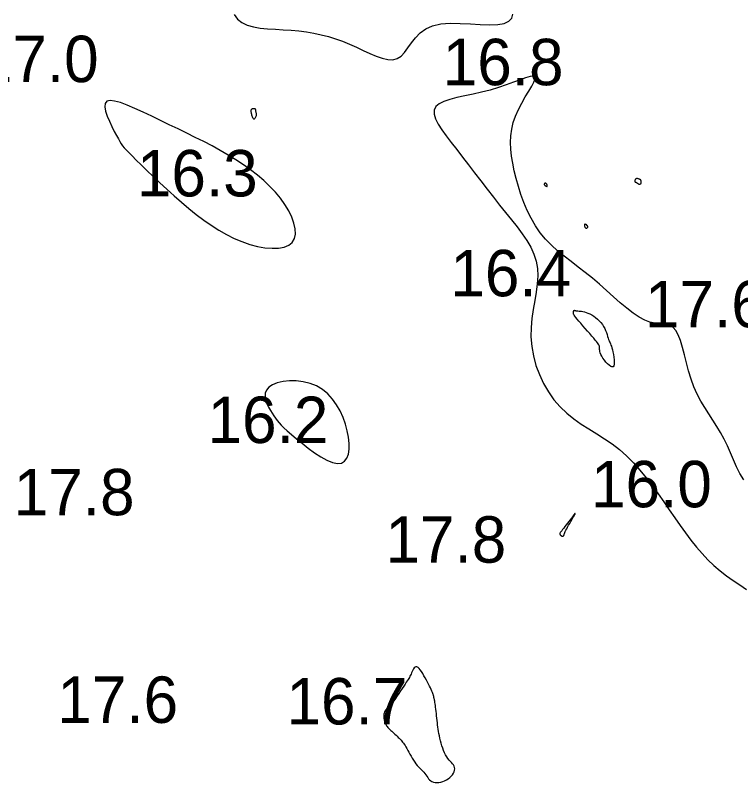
# Model space of a CAD drawing. Extents: x 3040093 to 3056816, y 408076 to 509144.
# Drawn here: x 3045488.3 to 3045566.4, y 434025.2 to 434107.9 of the extents above; entities that cross this region are included whole.
import ezdxf

# ---------------------------------------------------------------- set-up
doc = ezdxf.new("R2010")
doc.units = 0
doc.layers.add('V-CHAN-CONT-EL17', color=7, linetype='Continuous')
doc.layers.add('V-TOPO-SOUN-0610', color=7, linetype='Continuous')

msp = doc.modelspace()

# ---------------------------------------------------------------- linework, layer by layer
at = {"layer": 'V-CHAN-CONT-EL17'}
for points in [[(3045511.894, 434107.966), (3045512.24, 434107.481), (3045512.706, 434107.108), (3045513.282, 434106.836), (3045513.95, 434106.645), (3045514.69, 434106.517), (3045515.484, 434106.435), (3045516.315, 434106.381), (3045517.164, 434106.335), (3045518.013, 434106.281), (3045518.846, 434106.202), (3045519.663, 434106.095), (3045520.464, 434105.958), (3045521.252, 434105.79), (3045522.029, 434105.591), (3045522.795, 434105.358), (3045523.554, 434105.092), (3045524.307, 434104.789), (3045525.054, 434104.455), (3045525.787, 434104.109), (3045526.5, 434103.777), (3045527.183, 434103.485), (3045527.828, 434103.258), (3045528.427, 434103.121), (3045528.971, 434103.1), (3045529.451, 434103.221), (3045529.867, 434103.498), (3045530.24, 434103.901), (3045530.6, 434104.392), (3045530.978, 434104.931), (3045531.401, 434105.477), (3045531.901, 434105.991), (3045532.505, 434106.433), (3045533.245, 434106.764), (3045534.136, 434106.956), (3045535.143, 434107.032), (3045536.22, 434107.026), (3045537.318, 434106.975), (3045538.39, 434106.914), (3045539.388, 434106.877), (3045540.265, 434106.9), (3045540.972, 434107.018), (3045541.474, 434107.256), (3045541.774, 434107.598), (3045541.887, 434108.019)], [(3045566.758, 434057.837), (3045566.34, 434058.526), (3045565.974, 434059.251), (3045565.641, 434059.999), (3045565.322, 434060.754), (3045564.999, 434061.503), (3045564.653, 434062.232), (3045564.27, 434062.931), (3045563.857, 434063.608), (3045563.425, 434064.274), (3045562.987, 434064.941), (3045562.552, 434065.621), (3045562.134, 434066.326), (3045561.743, 434067.067), (3045561.39, 434067.857), (3045561.085, 434068.701), (3045560.819, 434069.577), (3045560.582, 434070.457), (3045560.363, 434071.313), (3045560.152, 434072.117), (3045559.938, 434072.841), (3045559.71, 434073.457), (3045559.457, 434073.936), (3045559.171, 434074.262), (3045558.849, 434074.46), (3045558.49, 434074.567), (3045558.092, 434074.621), (3045557.655, 434074.659), (3045557.178, 434074.716), (3045556.658, 434074.831), (3045556.096, 434075.039), (3045555.492, 434075.369), (3045554.849, 434075.808), (3045554.172, 434076.336), (3045553.466, 434076.932), (3045552.737, 434077.573), (3045551.989, 434078.24), (3045551.228, 434078.91), (3045550.458, 434079.562), (3045549.686, 434080.181), (3045548.918, 434080.774), (3045548.162, 434081.353), (3045547.426, 434081.931), (3045546.717, 434082.519), (3045546.045, 434083.13), (3045545.416, 434083.776), (3045544.838, 434084.47), (3045544.317, 434085.22), (3045543.852, 434086.019), (3045543.439, 434086.853), (3045543.076, 434087.712), (3045542.759, 434088.583), (3045542.485, 434089.454), (3045542.25, 434090.314), (3045542.052, 434091.151), (3045541.889, 434091.954), (3045541.764, 434092.728), (3045541.685, 434093.477), (3045541.657, 434094.206), (3045541.687, 434094.921), (3045541.78, 434095.626), (3045541.943, 434096.328), (3045542.181, 434097.032), (3045542.494, 434097.738), (3045542.857, 434098.432), (3045543.237, 434099.095), (3045543.603, 434099.707), (3045543.921, 434100.249), (3045544.16, 434100.703), (3045544.288, 434101.049), (3045544.272, 434101.269), (3045544.089, 434101.349), (3045543.748, 434101.308), (3045543.269, 434101.168), (3045542.67, 434100.954), (3045541.97, 434100.69), (3045541.186, 434100.399), (3045540.338, 434100.105), (3045539.444, 434099.833), (3045538.524, 434099.599), (3045537.603, 434099.396), (3045536.71, 434099.211), (3045535.87, 434099.028), (3045535.112, 434098.835), (3045534.462, 434098.616), (3045533.947, 434098.359), (3045533.595, 434098.049), (3045533.424, 434097.675), (3045533.423, 434097.236), (3045533.572, 434096.737), (3045533.849, 434096.179), (3045534.236, 434095.567), (3045534.711, 434094.901), (3045535.255, 434094.186), (3045535.848, 434093.424), (3045536.472, 434092.62), (3045537.117, 434091.782), (3045537.779, 434090.921), (3045538.452, 434090.048), (3045539.128, 434089.171), (3045539.802, 434088.303), (3045540.468, 434087.453), (3045541.119, 434086.632), (3045541.749, 434085.846), (3045542.347, 434085.09), (3045542.899, 434084.354), (3045543.394, 434083.627), (3045543.82, 434082.901), (3045544.164, 434082.166), (3045544.414, 434081.413), (3045544.557, 434080.63), (3045544.588, 434079.812), (3045544.529, 434078.959), (3045544.407, 434078.073), (3045544.25, 434077.156), (3045544.087, 434076.213), (3045543.945, 434075.245), (3045543.852, 434074.255), (3045543.837, 434073.246), (3045543.921, 434072.223), (3045544.105, 434071.196), (3045544.383, 434070.179), (3045544.748, 434069.185), (3045545.196, 434068.229), (3045545.721, 434067.322), (3045546.317, 434066.479), (3045546.977, 434065.713), (3045547.696, 434065.031), (3045548.463, 434064.419), (3045549.264, 434063.858), (3045550.09, 434063.326), (3045550.926, 434062.804), (3045551.761, 434062.272), (3045552.584, 434061.709), (3045553.382, 434061.097), (3045554.146, 434060.419), (3045554.877, 434059.681), (3045555.577, 434058.895), (3045556.25, 434058.071), (3045556.9, 434057.22), (3045557.529, 434056.353), (3045558.141, 434055.48), (3045558.74, 434054.613), (3045559.328, 434053.76), (3045559.91, 434052.928), (3045560.492, 434052.121), (3045561.077, 434051.344), (3045561.671, 434050.6), (3045562.278, 434049.894), (3045562.903, 434049.231), (3045563.551, 434048.614), (3045564.224, 434048.046), (3045564.919, 434047.517), (3045565.63, 434047.014), (3045566.349, 434046.524), (3045567.072, 434046.035)]]:
    msp.add_lwpolyline(points, dxfattribs=at)
for points in [[(3045506.998, 434087.081), (3045507.797, 434086.438), (3045508.6, 434085.831), (3045509.407, 434085.265), (3045510.22, 434084.744), (3045511.04, 434084.273), (3045511.868, 434083.859), (3045512.706, 434083.505), (3045513.552, 434083.217), (3045514.39, 434083), (3045515.199, 434082.858), (3045515.961, 434082.796), (3045516.656, 434082.817), (3045517.264, 434082.928), (3045517.766, 434083.131), (3045518.143, 434083.432), (3045518.379, 434083.831), (3045518.48, 434084.317), (3045518.458, 434084.874), (3045518.322, 434085.486), (3045518.084, 434086.138), (3045517.754, 434086.813), (3045517.342, 434087.498), (3045516.861, 434088.175), (3045516.318, 434088.831), (3045515.721, 434089.466), (3045515.073, 434090.079), (3045514.378, 434090.671), (3045513.642, 434091.243), (3045512.87, 434091.794), (3045512.064, 434092.326), (3045511.231, 434092.84), (3045510.375, 434093.335), (3045509.497, 434093.816), (3045508.602, 434094.284), (3045507.691, 434094.744), (3045506.767, 434095.197), (3045505.833, 434095.648), (3045504.892, 434096.099), (3045503.946, 434096.553), (3045503, 434097.01), (3045502.074, 434097.452), (3045501.19, 434097.859), (3045500.37, 434098.209), (3045499.636, 434098.482), (3045499.009, 434098.656), (3045498.512, 434098.71), (3045498.168, 434098.624), (3045497.989, 434098.385), (3045497.955, 434098.018), (3045498.038, 434097.554), (3045498.211, 434097.027), (3045498.443, 434096.469), (3045498.707, 434095.913), (3045498.975, 434095.391), (3045499.217, 434094.936), (3045499.414, 434094.571), (3045499.576, 434094.282), (3045499.722, 434094.043), (3045499.872, 434093.83), (3045500.045, 434093.618), (3045500.259, 434093.383), (3045500.534, 434093.101), (3045500.888, 434092.746), (3045501.336, 434092.301), (3045501.87, 434091.775), (3045502.478, 434091.181), (3045503.148, 434090.537), (3045503.867, 434089.857), (3045504.624, 434089.156), (3045505.406, 434088.45), (3045506.2, 434087.754)], [(3045514.008, 434096.739), (3045514.054, 434096.753), (3045514.1, 434096.785), (3045514.144, 434096.831), (3045514.185, 434096.887), (3045514.221, 434096.95), (3045514.25, 434097.017), (3045514.271, 434097.084), (3045514.282, 434097.148), (3045514.285, 434097.209), (3045514.282, 434097.267), (3045514.274, 434097.322), (3045514.262, 434097.375), (3045514.25, 434097.425), (3045514.238, 434097.474), (3045514.229, 434097.521), (3045514.222, 434097.567), (3045514.218, 434097.61), (3045514.215, 434097.652), (3045514.209, 434097.69), (3045514.2, 434097.724), (3045514.186, 434097.754), (3045514.164, 434097.78), (3045514.133, 434097.8), (3045514.092, 434097.814), (3045514.043, 434097.822), (3045513.988, 434097.824), (3045513.93, 434097.821), (3045513.872, 434097.812), (3045513.818, 434097.798), (3045513.769, 434097.778), (3045513.728, 434097.753), (3045513.698, 434097.723), (3045513.679, 434097.687), (3045513.668, 434097.646), (3045513.666, 434097.597), (3045513.67, 434097.542), (3045513.681, 434097.48), (3045513.696, 434097.41), (3045513.714, 434097.331), (3045513.736, 434097.245), (3045513.76, 434097.154), (3045513.786, 434097.062), (3045513.816, 434096.975), (3045513.848, 434096.895), (3045513.883, 434096.828), (3045513.922, 434096.777), (3045513.963, 434096.746)], [(3045555.478, 434089.709), (3045555.514, 434089.705), (3045555.552, 434089.706), (3045555.588, 434089.712), (3045555.622, 434089.724), (3045555.653, 434089.74), (3045555.68, 434089.761), (3045555.7, 434089.788), (3045555.713, 434089.819), (3045555.721, 434089.854), (3045555.723, 434089.891), (3045555.722, 434089.93), (3045555.717, 434089.968), (3045555.71, 434090.005), (3045555.703, 434090.039), (3045555.695, 434090.07), (3045555.689, 434090.095), (3045555.682, 434090.116), (3045555.674, 434090.133), (3045555.664, 434090.149), (3045555.65, 434090.163), (3045555.63, 434090.177), (3045555.605, 434090.192), (3045555.572, 434090.209), (3045555.531, 434090.228), (3045555.483, 434090.249), (3045555.431, 434090.269), (3045555.376, 434090.286), (3045555.32, 434090.299), (3045555.265, 434090.305), (3045555.213, 434090.304), (3045555.167, 434090.292), (3045555.127, 434090.27), (3045555.094, 434090.238), (3045555.068, 434090.199), (3045555.049, 434090.156), (3045555.036, 434090.112), (3045555.029, 434090.068), (3045555.029, 434090.027), (3045555.035, 434089.992), (3045555.047, 434089.965), (3045555.063, 434089.944), (3045555.084, 434089.929), (3045555.109, 434089.917), (3045555.135, 434089.908), (3045555.163, 434089.898), (3045555.191, 434089.888), (3045555.219, 434089.875), (3045555.246, 434089.858), (3045555.272, 434089.838), (3045555.298, 434089.816), (3045555.324, 434089.793), (3045555.351, 434089.771), (3045555.38, 434089.75), (3045555.41, 434089.732), (3045555.442, 434089.718)], [(3045545.599, 434089.481), (3045545.602, 434089.506), (3045545.599, 434089.537), (3045545.589, 434089.573), (3045545.576, 434089.612), (3045545.559, 434089.65), (3045545.54, 434089.686), (3045545.52, 434089.718), (3045545.502, 434089.744), (3045545.484, 434089.765), (3045545.467, 434089.78), (3045545.45, 434089.791), (3045545.434, 434089.798), (3045545.419, 434089.802), (3045545.403, 434089.803), (3045545.389, 434089.803), (3045545.374, 434089.802), (3045545.36, 434089.799), (3045545.347, 434089.795), (3045545.334, 434089.789), (3045545.322, 434089.782), (3045545.31, 434089.773), (3045545.3, 434089.763), (3045545.29, 434089.751), (3045545.282, 434089.736), (3045545.276, 434089.72), (3045545.272, 434089.703), (3045545.272, 434089.683), (3045545.276, 434089.662), (3045545.285, 434089.639), (3045545.301, 434089.615), (3045545.323, 434089.589), (3045545.352, 434089.562), (3045545.387, 434089.535), (3045545.425, 434089.51), (3045545.464, 434089.489), (3045545.501, 434089.472), (3045545.536, 434089.461), (3045545.565, 434089.458), (3045545.586, 434089.464)], [(3045549.87, 434084.971), (3045549.89, 434084.986), (3045549.908, 434085.003), (3045549.925, 434085.023), (3045549.94, 434085.043), (3045549.952, 434085.063), (3045549.962, 434085.083), (3045549.967, 434085.102), (3045549.969, 434085.12), (3045549.967, 434085.135), (3045549.963, 434085.149), (3045549.956, 434085.162), (3045549.948, 434085.173), (3045549.938, 434085.183), (3045549.929, 434085.191), (3045549.919, 434085.199), (3045549.91, 434085.205), (3045549.902, 434085.211), (3045549.895, 434085.216), (3045549.888, 434085.22), (3045549.883, 434085.225), (3045549.879, 434085.229), (3045549.876, 434085.234), (3045549.874, 434085.239), (3045549.874, 434085.245), (3045549.874, 434085.251), (3045549.873, 434085.259), (3045549.87, 434085.267), (3045549.865, 434085.277), (3045549.857, 434085.288), (3045549.844, 434085.301), (3045549.825, 434085.314), (3045549.801, 434085.33), (3045549.772, 434085.345), (3045549.74, 434085.359), (3045549.707, 434085.369), (3045549.675, 434085.376), (3045549.646, 434085.376), (3045549.622, 434085.369), (3045549.605, 434085.352), (3045549.595, 434085.326), (3045549.593, 434085.291), (3045549.597, 434085.25), (3045549.607, 434085.205), (3045549.621, 434085.159), (3045549.638, 434085.113), (3045549.658, 434085.07), (3045549.678, 434085.033), (3045549.7, 434085.002), (3045549.721, 434084.979), (3045549.743, 434084.962), (3045549.764, 434084.951), (3045549.786, 434084.945), (3045549.807, 434084.945), (3045549.828, 434084.95), (3045549.849, 434084.958)], [(3045551.215, 434072.234), (3045551.19, 434072.312), (3045551.149, 434072.398), (3045551.089, 434072.494), (3045551.007, 434072.608), (3045550.9, 434072.744), (3045550.765, 434072.908), (3045550.598, 434073.104), (3045550.398, 434073.336), (3045550.173, 434073.596), (3045549.932, 434073.873), (3045549.684, 434074.158), (3045549.44, 434074.44), (3045549.208, 434074.709), (3045548.998, 434074.955), (3045548.82, 434075.168), (3045548.68, 434075.34), (3045548.576, 434075.474), (3045548.503, 434075.576), (3045548.455, 434075.651), (3045548.427, 434075.705), (3045548.414, 434075.743), (3045548.411, 434075.772), (3045548.413, 434075.795), (3045548.415, 434075.819), (3045548.416, 434075.844), (3045548.417, 434075.869), (3045548.419, 434075.895), (3045548.42, 434075.921), (3045548.423, 434075.946), (3045548.426, 434075.971), (3045548.431, 434075.995), (3045548.437, 434076.018), (3045548.444, 434076.039), (3045548.453, 434076.059), (3045548.463, 434076.076), (3045548.473, 434076.09), (3045548.485, 434076.101), (3045548.497, 434076.108), (3045548.51, 434076.111), (3045548.523, 434076.11), (3045548.54, 434076.106), (3045548.561, 434076.098), (3045548.589, 434076.088), (3045548.626, 434076.077), (3045548.674, 434076.066), (3045548.736, 434076.056), (3045548.813, 434076.047), (3045548.907, 434076.039), (3045549.018, 434076.032), (3045549.145, 434076.02), (3045549.287, 434076.002), (3045549.443, 434075.975), (3045549.611, 434075.936), (3045549.792, 434075.882), (3045549.984, 434075.81), (3045550.186, 434075.718), (3045550.393, 434075.606), (3045550.603, 434075.476), (3045550.81, 434075.329), (3045551.011, 434075.165), (3045551.201, 434074.987), (3045551.377, 434074.794), (3045551.534, 434074.589), (3045551.67, 434074.373), (3045551.785, 434074.151), (3045551.883, 434073.926), (3045551.967, 434073.705), (3045552.038, 434073.492), (3045552.101, 434073.292), (3045552.156, 434073.109), (3045552.208, 434072.95), (3045552.259, 434072.816), (3045552.309, 434072.7), (3045552.359, 434072.593), (3045552.409, 434072.485), (3045552.46, 434072.369), (3045552.511, 434072.233), (3045552.563, 434072.069), (3045552.617, 434071.868), (3045552.672, 434071.624), (3045552.724, 434071.35), (3045552.768, 434071.063), (3045552.798, 434070.78), (3045552.809, 434070.518), (3045552.797, 434070.293), (3045552.756, 434070.123), (3045552.681, 434070.023), (3045552.57, 434070.007), (3045552.429, 434070.065), (3045552.267, 434070.182), (3045552.093, 434070.345), (3045551.918, 434070.54), (3045551.749, 434070.752), (3045551.597, 434070.968), (3045551.471, 434071.173), (3045551.376, 434071.355), (3045551.311, 434071.516), (3045551.27, 434071.657), (3045551.247, 434071.78), (3045551.237, 434071.89), (3045551.234, 434071.987), (3045551.233, 434072.075), (3045551.228, 434072.156)], [(3045523.443, 434059.638), (3045523.779, 434059.84), (3045524.023, 434060.175), (3045524.18, 434060.623), (3045524.258, 434061.163), (3045524.259, 434061.776), (3045524.191, 434062.443), (3045524.057, 434063.143), (3045523.863, 434063.857), (3045523.608, 434064.569), (3045523.292, 434065.264), (3045522.914, 434065.928), (3045522.472, 434066.544), (3045521.966, 434067.097), (3045521.395, 434067.573), (3045520.758, 434067.956), (3045520.059, 434068.235), (3045519.321, 434068.413), (3045518.571, 434068.499), (3045517.836, 434068.501), (3045517.145, 434068.425), (3045516.524, 434068.28), (3045516, 434068.074), (3045515.602, 434067.814), (3045515.348, 434067.508), (3045515.224, 434067.168), (3045515.209, 434066.804), (3045515.281, 434066.427), (3045515.417, 434066.048), (3045515.595, 434065.679), (3045515.793, 434065.33), (3045515.99, 434065.012), (3045516.168, 434064.733), (3045516.339, 434064.481), (3045516.516, 434064.242), (3045516.716, 434064.003), (3045516.953, 434063.747), (3045517.244, 434063.461), (3045517.604, 434063.13), (3045518.047, 434062.739), (3045518.584, 434062.281), (3045519.194, 434061.78), (3045519.854, 434061.267), (3045520.538, 434060.771), (3045521.221, 434060.325), (3045521.878, 434059.959), (3045522.483, 434059.703), (3045523.011, 434059.589)], [(3045547.376, 434051.855), (3045547.39, 434051.89), (3045547.406, 434051.936), (3045547.426, 434051.994), (3045547.454, 434052.069), (3045547.492, 434052.161), (3045547.543, 434052.275), (3045547.61, 434052.413), (3045547.694, 434052.575), (3045547.793, 434052.757), (3045547.901, 434052.951), (3045548.014, 434053.149), (3045548.126, 434053.345), (3045548.234, 434053.532), (3045548.333, 434053.701), (3045548.417, 434053.847), (3045548.484, 434053.962), (3045548.534, 434054.051), (3045548.57, 434054.115), (3045548.594, 434054.16), (3045548.608, 434054.189), (3045548.616, 434054.206), (3045548.618, 434054.215), (3045548.618, 434054.22), (3045548.617, 434054.224), (3045548.616, 434054.227), (3045548.614, 434054.23), (3045548.612, 434054.232), (3045548.61, 434054.233), (3045548.607, 434054.233), (3045548.604, 434054.233), (3045548.6, 434054.231), (3045548.596, 434054.228), (3045548.588, 434054.22), (3045548.574, 434054.203), (3045548.55, 434054.174), (3045548.515, 434054.129), (3045548.465, 434054.064), (3045548.398, 434053.977), (3045548.31, 434053.862), (3045548.201, 434053.718), (3045548.073, 434053.551), (3045547.934, 434053.369), (3045547.789, 434053.178), (3045547.642, 434052.987), (3045547.501, 434052.803), (3045547.371, 434052.633), (3045547.256, 434052.484), (3045547.162, 434052.364), (3045547.089, 434052.268), (3045547.033, 434052.194), (3045546.993, 434052.138), (3045546.967, 434052.095), (3045546.953, 434052.061), (3045546.949, 434052.033), (3045546.954, 434052.006), (3045546.965, 434051.977), (3045546.981, 434051.947), (3045547.001, 434051.917), (3045547.026, 434051.887), (3045547.054, 434051.858), (3045547.083, 434051.831), (3045547.115, 434051.808), (3045547.147, 434051.79), (3045547.179, 434051.776), (3045547.21, 434051.768), (3045547.241, 434051.765), (3045547.27, 434051.767), (3045547.297, 434051.775), (3045547.321, 434051.787), (3045547.343, 434051.804), (3045547.361, 434051.827)], [(3045528.233, 434031.447), (3045528.291, 434031.348), (3045528.353, 434031.259), (3045528.421, 434031.177), (3045528.494, 434031.099), (3045528.574, 434031.021), (3045528.661, 434030.941), (3045528.756, 434030.854), (3045528.859, 434030.759), (3045528.969, 434030.657), (3045529.084, 434030.549), (3045529.201, 434030.438), (3045529.319, 434030.326), (3045529.435, 434030.214), (3045529.548, 434030.104), (3045529.656, 434029.999), (3045529.756, 434029.899), (3045529.85, 434029.802), (3045529.94, 434029.704), (3045530.027, 434029.601), (3045530.113, 434029.491), (3045530.2, 434029.369), (3045530.289, 434029.232), (3045530.383, 434029.076), (3045530.481, 434028.898), (3045530.586, 434028.704), (3045530.696, 434028.496), (3045530.811, 434028.281), (3045530.931, 434028.062), (3045531.057, 434027.845), (3045531.187, 434027.635), (3045531.323, 434027.435), (3045531.463, 434027.25), (3045531.606, 434027.079), (3045531.749, 434026.919), (3045531.892, 434026.767), (3045532.032, 434026.622), (3045532.166, 434026.48), (3045532.294, 434026.34), (3045532.412, 434026.198), (3045532.521, 434026.054), (3045532.623, 434025.91), (3045532.723, 434025.77), (3045532.824, 434025.639), (3045532.932, 434025.518), (3045533.051, 434025.414), (3045533.184, 434025.329), (3045533.337, 434025.267), (3045533.512, 434025.232), (3045533.705, 434025.222), (3045533.91, 434025.237), (3045534.123, 434025.275), (3045534.338, 434025.335), (3045534.55, 434025.416), (3045534.753, 434025.516), (3045534.942, 434025.635), (3045535.113, 434025.77), (3045535.262, 434025.918), (3045535.388, 434026.075), (3045535.49, 434026.238), (3045535.566, 434026.402), (3045535.614, 434026.565), (3045535.632, 434026.721), (3045535.619, 434026.868), (3045535.574, 434027.003), (3045535.502, 434027.13), (3045535.406, 434027.253), (3045535.294, 434027.378), (3045535.169, 434027.509), (3045535.038, 434027.653), (3045534.905, 434027.813), (3045534.775, 434027.995), (3045534.653, 434028.202), (3045534.54, 434028.432), (3045534.436, 434028.678), (3045534.34, 434028.938), (3045534.253, 434029.205), (3045534.173, 434029.475), (3045534.102, 434029.744), (3045534.039, 434030.007), (3045533.984, 434030.259), (3045533.936, 434030.503), (3045533.894, 434030.74), (3045533.856, 434030.973), (3045533.823, 434031.204), (3045533.793, 434031.436), (3045533.765, 434031.671), (3045533.738, 434031.911), (3045533.711, 434032.158), (3045533.685, 434032.407), (3045533.659, 434032.656), (3045533.633, 434032.899), (3045533.607, 434033.132), (3045533.581, 434033.35), (3045533.556, 434033.549), (3045533.531, 434033.725), (3045533.506, 434033.874), (3045533.483, 434033.999), (3045533.46, 434034.102), (3045533.44, 434034.185), (3045533.421, 434034.253), (3045533.406, 434034.309), (3045533.394, 434034.354), (3045533.386, 434034.392), (3045533.382, 434034.426), (3045533.38, 434034.46), (3045533.378, 434034.496), (3045533.374, 434034.539), (3045533.365, 434034.59), (3045533.349, 434034.654), (3045533.323, 434034.733), (3045533.287, 434034.832), (3045533.237, 434034.952), (3045533.174, 434035.092), (3045533.1, 434035.251), (3045533.014, 434035.428), (3045532.919, 434035.62), (3045532.814, 434035.825), (3045532.702, 434036.043), (3045532.582, 434036.271), (3045532.456, 434036.507), (3045532.325, 434036.743), (3045532.193, 434036.971), (3045532.06, 434037.183), (3045531.929, 434037.37), (3045531.802, 434037.524), (3045531.68, 434037.637), (3045531.566, 434037.7), (3045531.462, 434037.707), (3045531.366, 434037.666), (3045531.279, 434037.586), (3045531.198, 434037.475), (3045531.124, 434037.344), (3045531.055, 434037.201), (3045530.99, 434037.055), (3045530.929, 434036.917), (3045530.871, 434036.792), (3045530.811, 434036.677), (3045530.749, 434036.566), (3045530.68, 434036.452), (3045530.602, 434036.329), (3045530.511, 434036.191), (3045530.405, 434036.03), (3045530.281, 434035.841), (3045530.136, 434035.62), (3045529.975, 434035.373), (3045529.8, 434035.108), (3045529.617, 434034.834), (3045529.43, 434034.56), (3045529.243, 434034.294), (3045529.061, 434034.045), (3045528.886, 434033.821), (3045528.725, 434033.628), (3045528.576, 434033.463), (3045528.443, 434033.32), (3045528.325, 434033.193), (3045528.223, 434033.076), (3045528.139, 434032.963), (3045528.072, 434032.847), (3045528.025, 434032.723), (3045527.997, 434032.587), (3045527.987, 434032.44), (3045527.992, 434032.287), (3045528.011, 434032.132), (3045528.041, 434031.977), (3045528.08, 434031.828), (3045528.127, 434031.687), (3045528.178, 434031.559)]]:
    msp.add_lwpolyline(points, close=True, dxfattribs=at)

# ---------------------------------------------------------------- texts
at = {"layer": 'V-TOPO-SOUN-0610'}
for s, p in [('17.0 ', (3045484.273, 434100.69)), ('16.8 ', (3045534.343, 434100.36)), ('16.3 ', (3045501.403, 434088.38)), ('16.4 ', (3045535.163, 434077.62)), ('17.6 ', (3045556.123, 434074.28)), ('16.2 ', (3045509.013, 434061.81)), ('16.0 ', (3045550.313, 434054.89)), ('17.8 ', (3045488.143, 434054.03)), ('17.8 ', (3045528.173, 434048.92)), ('17.6 ', (3045492.833, 434031.66)), ('16.7 ', (3045517.513, 434031.49))]:
    msp.add_text(s, height=5, dxfattribs=at).set_placement(p)

doc.saveas('drawing.dxf')
